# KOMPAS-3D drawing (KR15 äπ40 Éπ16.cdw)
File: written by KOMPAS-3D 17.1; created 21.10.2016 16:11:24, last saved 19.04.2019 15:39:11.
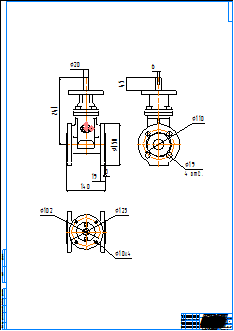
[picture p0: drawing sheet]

Sheet 1: A0, portrait

Title block, sheet 1: name: KR15 Ду40 Ру16; material: Внимание! Данный продукт является объектом авторского права ООО «Торговый Дом АДЛ». / Запрещается изменение, копирование, распространение / (в том числе путем копирования на другие сайты и ресурсы в Интернете) / или любое иное использование информации и объектов без предварительного / согласия правообладателя (ООО «Торговый Дом АДЛ»).; mass: 14,1; sheets: 1; organisation: ООО "Торговый дом АДЛ"; sheet format: A0; stored path: \\adlc.lan\data\АДЛ_ПКД\3D-модели\ADL production\Клиновые задвижки серии KR ГРАНАР\Клиновые задвижки KR15\С голым штоком\KOMPAS 2D\KR15 Ду40 Ру16.cdw

Views: Спереди 4, Проекционный вид 5, Проекционный вид 6
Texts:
  Klimkovich
  ADL
Dimensions and other numbers on the sheet: 19; 20; 241; 125; 102; 10; 110; 4 отв.; 45; 6; 140; 3; 150; 1:1; 1; 14,1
